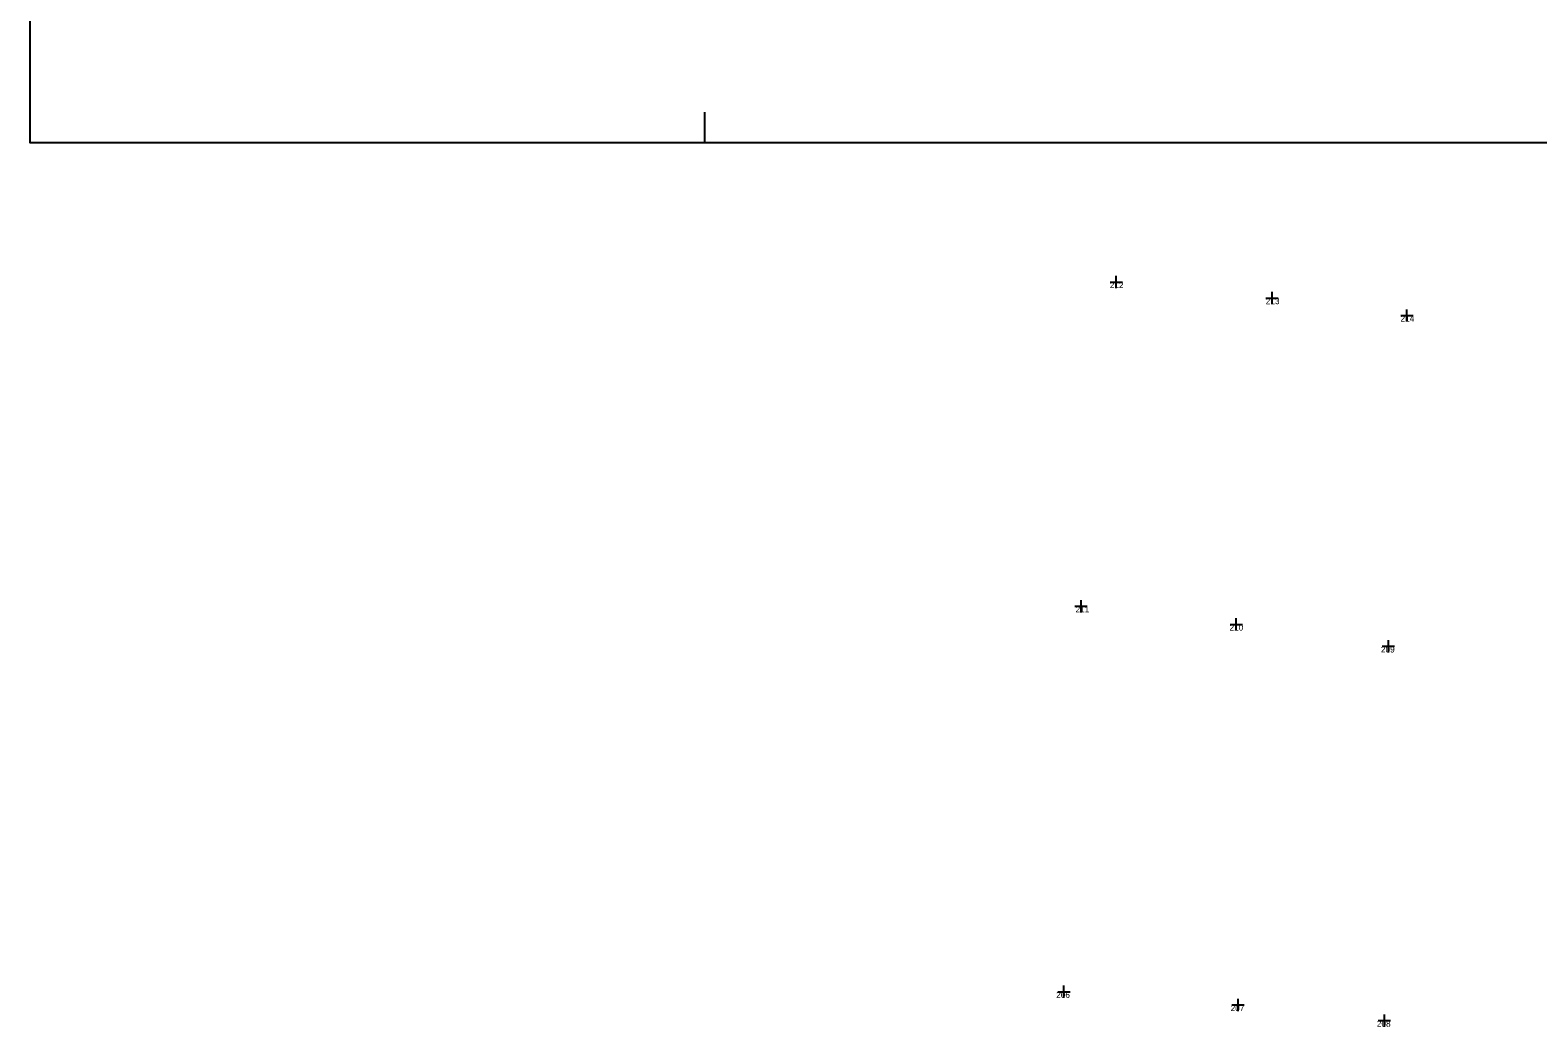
# Model space of a CAD drawing. Extents: x -706631 to -706106, y -1036183 to -1035074.
# Drawn here: x -706353.1 to -706230.8, y -1036071.7 to -1035990.8 of the extents above; entities that cross this region are included whole.
import ezdxf

# ---------------------------------------------------------------- set-up
doc = ezdxf.new("R2010")
doc.units = 0
doc.layers.add('Vrstva 54', color=7, linetype='Continuous')
doc.layers.add('čísla bodu', color=7, linetype='Continuous')

msp = doc.modelspace()

# ---------------------------------------------------------------- linework, layer by layer
at = {"layer": 'Vrstva 54'}
msp.add_line((-706298.39, -1035999.96), (-706298.39, -1035997.46), dxfattribs=at)
msp.add_lwpolyline([(-706353.14, -1035579.96), (-706108.39, -1035579.96), (-706108.39, -1035999.96), (-706353.14, -1035999.96)], close=True, dxfattribs=at)
at = {"layer": 'čísla bodu'}
for p, q in [((-706264.99, -1036011.75), (-706264.99, -1036010.75)), ((-706265.49, -1036011.25), (-706264.49, -1036011.25)), ((-706264.99, -1036011.25), (-706264.99, -1036011.25)), ((-706252.33, -1036013.05), (-706252.33, -1036012.05)), ((-706252.83, -1036012.55), (-706251.83, -1036012.55)), ((-706252.33, -1036012.55), (-706252.33, -1036012.55)), ((-706241.89, -1036013.97), (-706240.89, -1036013.97)), ((-706241.39, -1036014.47), (-706241.39, -1036013.47)), ((-706241.39, -1036013.97), (-706241.39, -1036013.97)), ((-706268.34, -1036037.58), (-706267.34, -1036037.58)), ((-706267.84, -1036038.08), (-706267.84, -1036037.08)), ((-706267.84, -1036037.58), (-706267.84, -1036037.58)), ((-706255.25, -1036039.55), (-706255.25, -1036038.55)), ((-706255.75, -1036039.05), (-706254.75, -1036039.05)), ((-706255.25, -1036039.05), (-706255.25, -1036039.05)), ((-706243.39, -1036040.83), (-706242.39, -1036040.83)), ((-706242.89, -1036041.33), (-706242.89, -1036040.33)), ((-706242.89, -1036040.83), (-706242.89, -1036040.83)), ((-706269.73, -1036068.88), (-706268.73, -1036068.88)), ((-706269.23, -1036069.38), (-706269.23, -1036068.38)), ((-706269.23, -1036068.88), (-706269.23, -1036068.88)), ((-706255.09, -1036070.45), (-706255.09, -1036069.45)), ((-706255.59, -1036069.95), (-706254.59, -1036069.95)), ((-706255.09, -1036069.95), (-706255.09, -1036069.95)), ((-706243.22, -1036071.72), (-706243.22, -1036070.72)), ((-706243.72, -1036071.22), (-706242.72, -1036071.22)), ((-706243.22, -1036071.22), (-706243.22, -1036071.22))]:
    msp.add_line(p, q, dxfattribs=at)

# ---------------------------------------------------------------- texts
for s, p in [('212', (-706265.51, -1036011.75)), ('213', (-706252.85, -1036013.05)), ('214', (-706241.91, -1036014.47)), ('211', (-706268.29, -1036038.08)), ('210', (-706255.79, -1036039.55)), ('209', (-706243.5, -1036041.33)), ('206', (-706269.86, -1036069.38)), ('207', (-706255.7, -1036070.45)), ('208', (-706243.83, -1036071.72))]:
    msp.add_text(s, height=0.5, dxfattribs=at).set_placement(p)

doc.saveas('drawing.dxf')
